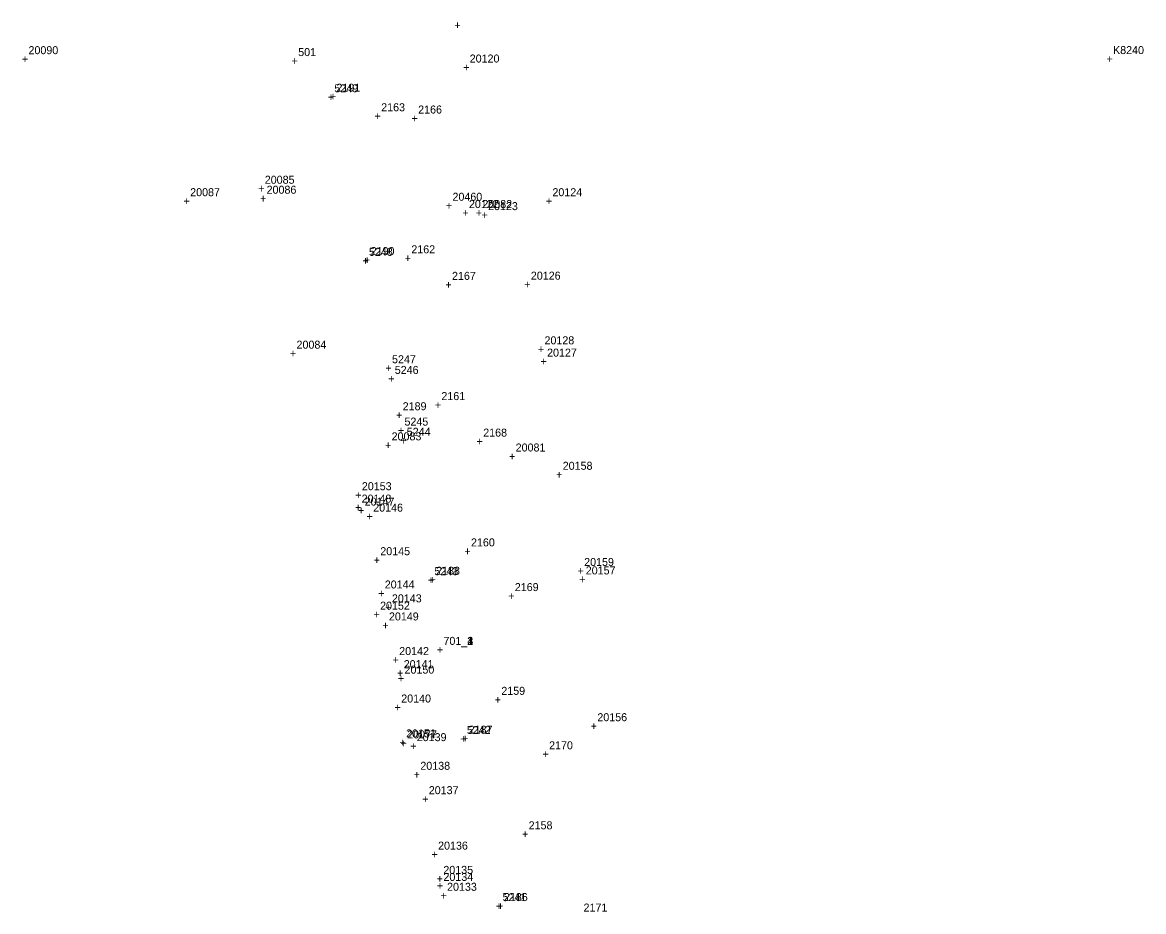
# Model space of a CAD drawing. Extents: x 1036751 to 1042192, y 772604 to 785439.
# Drawn here: x 1041410.1 to 1041760.3, y 774203.6 to 774481.3 of the extents above; entities that cross this region are included whole.
import ezdxf

# ---------------------------------------------------------------- set-up
doc = ezdxf.new("R2010")
doc.units = 0
for name, color, linetype in [('S_Buildings', 7, 'Continuous'), ('S_Buildings_SillElevation', 7, 'Continuous'), ('S_Control_Temp_Traverse', 7, 'Continuous'), ('S_Control_Traverse_Point', 7, 'Continuous'), ('S_Curb_Type_2', 7, 'Continuous'), ('S_Property_IronPipeFound', 7, 'Continuous'), ('S_Property_StoneWall', 7, 'Continuous'), ('S_Roadway_Centerline', 7, 'Continuous'), ('S_Roadway_Edge_Pavement', 7, 'Continuous'), ('S_Roadway_Monument', 7, 'Continuous'), ('S_Trees_Decid_Pay', 7, 'Continuous'), ('S_Utilities_Pole_Power', 7, 'Continuous'), ('S_Utilities_UG_Sanitary_MH', 7, 'Continuous')]:
    doc.layers.add(name, color=color, linetype=linetype)

msp = doc.modelspace()

# ---------------------------------------------------------------- texts
at = {"layer": 'S_Buildings'}
for s, p in [('20120', (1041549.8, 774468.8)), ('+', (1041547.74, 774466.05)), ('20085', (1041485.78, 774430.94)), ('20087', (1041462.48, 774427.05)), ('+', (1041483.72, 774428.19)), ('+', (1041460.42, 774424.3)), ('+', (1041566.84, 774398.22)), ('20126', (1041568.9, 774400.97)), ('20084', (1041495.7, 774379.42)), ('20127', (1041573.97, 774376.94)), ('+', (1041493.64, 774376.67)), ('+', (1041571.91, 774374.19)), ('+', (1041576.78, 774338.84)), ('20158', (1041578.85, 774341.59)), ('20157', (1041586.05, 774308.91)), ('+', (1041583.99, 774306.16))]:
    msp.add_text(s, height=2.5, dxfattribs=at).set_placement(p)
at = {"layer": 'S_Buildings_SillElevation'}
for s, p in [('+', (1041545, 774479.23)), ('20086', (1041486.35, 774427.82)), ('+', (1041484.29, 774425.07)), ('20128', (1041573.16, 774380.78)), ('+', (1041571.1, 774378.03)), ('20159', (1041585.55, 774311.54)), ('+', (1041583.49, 774308.79))]:
    msp.add_text(s, height=2.5, dxfattribs=at).set_placement(p)
at = {"layer": 'S_Control_Temp_Traverse'}
for s, p in [('701', (1041541.6, 774286.89)), ('701', (1041541.6, 774286.89)), ('701_4', (1041541.6, 774286.89)), ('701_3', (1041541.6, 774286.89)), ('701_2', (1041541.6, 774286.89)), ('701_1', (1041541.6, 774286.89)), ('+', (1041539.54, 774284.15)), ('+', (1041539.54, 774284.15)), ('+', (1041539.54, 774284.15)), ('+', (1041539.54, 774284.15)), ('+', (1041539.54, 774284.15)), ('+', (1041539.54, 774284.15))]:
    msp.add_text(s, height=2.5, dxfattribs=at).set_placement(p)
at = {"layer": 'S_Control_Traverse_Point'}
for s, p in [('501', (1041496.22, 774470.82)), ('501', (1041496.22, 774470.82)), ('501', (1041496.22, 774470.82)), ('501', (1041496.22, 774470.82)), ('501', (1041496.22, 774470.82)), ('501', (1041496.22, 774470.82)), ('501', (1041496.22, 774470.82)), ('501', (1041496.22, 774470.82)), ('501', (1041496.22, 774470.82)), ('501', (1041496.22, 774470.82)), ('+', (1041494.16, 774468.07)), ('+', (1041494.16, 774468.07)), ('+', (1041494.16, 774468.07)), ('+', (1041494.16, 774468.07)), ('+', (1041494.16, 774468.07)), ('+', (1041494.16, 774468.07)), ('+', (1041494.16, 774468.07)), ('+', (1041494.16, 774468.07)), ('+', (1041494.16, 774468.07)), ('+', (1041494.16, 774468.07))]:
    msp.add_text(s, height=2.5, dxfattribs=at).set_placement(p)
at = {"layer": 'S_Curb_Type_2'}
for s, p in [('5249', (1041507.52, 774459.51)), ('+', (1041505.46, 774456.76)), ('5248', (1041518.33, 774408.42)), ('+', (1041516.27, 774405.67)), ('5247', (1041525.53, 774374.87)), ('+', (1041523.47, 774372.12)), ('5246', (1041526.38, 774371.53)), ('+', (1041524.32, 774368.78)), ('+', (1041527.36, 774352.64)), ('5245', (1041529.42, 774355.39)), ('5244', (1041530.12, 774352.21)), ('+', (1041528.06, 774349.46)), ('5243', (1041538.78, 774308.67)), ('+', (1041536.72, 774305.92)), ('5242', (1041548.91, 774259.06)), ('+', (1041546.85, 774256.31)), ('5241', (1041560.05, 774206.84)), ('+', (1041557.98, 774204.09))]:
    msp.add_text(s, height=2.5, dxfattribs=at).set_placement(p)
at = {"layer": 'S_Property_IronPipeFound'}
for s, p in [('20082', (1041553.75, 774423.35)), ('+', (1041551.69, 774420.6))]:
    msp.add_text(s, height=2.5, dxfattribs=at).set_placement(p)
at = {"layer": 'S_Property_StoneWall'}
for s, p in [('20124', (1041575.64, 774427.04)), ('20122', (1041549.56, 774423.35)), ('20123', (1041555.54, 774422.7)), ('+', (1041573.58, 774424.29)), ('+', (1041547.49, 774420.6)), ('+', (1041553.48, 774419.95)), ('20153', (1041516.11, 774335.21)), ('+', (1041514.05, 774332.46)), ('20152', (1041521.8, 774297.89)), ('+', (1041519.74, 774295.14)), ('20151', (1041529.92, 774257.99)), ('20077', (1041530.27, 774257.67)), ('+', (1041527.86, 774255.24)), ('+', (1041528.21, 774254.92))]:
    msp.add_text(s, height=2.5, dxfattribs=at).set_placement(p)
at = {"layer": 'S_Roadway_Centerline'}
for s, p in [('+', (1041520.09, 774450.83)), ('2163', (1041522.15, 774453.58)), ('2162', (1041531.56, 774409.2)), ('+', (1041529.5, 774406.45)), ('2161', (1041540.95, 774363.36)), ('+', (1041538.89, 774360.61)), ('2160', (1041550.2, 774317.66)), ('+', (1041548.14, 774314.91)), ('+', (1041557.61, 774268.54)), ('2159', (1041559.67, 774271.29)), ('+', (1041566.15, 774226.54)), ('2158', (1041568.21, 774229.29))]:
    msp.add_text(s, height=2.5, dxfattribs=at).set_placement(p)
at = {"layer": 'S_Roadway_Edge_Pavement'}
for s, p in [('2191', (1041508.17, 774459.69)), ('+', (1041506.1, 774456.94)), ('2166', (1041533.7, 774452.87)), ('+', (1041531.64, 774450.12)), ('2190', (1041518.86, 774408.65)), ('+', (1041516.79, 774405.9)), ('+', (1041542.21, 774398.16)), ('2167', (1041544.27, 774400.91)), ('2189', (1041528.86, 774360.19)), ('+', (1041526.8, 774357.44)), ('+', (1041551.95, 774349.2)), ('2168', (1041554.02, 774351.95)), ('2188', (1041539.32, 774308.8)), ('+', (1041537.26, 774306.05)), ('2169', (1041563.89, 774303.7)), ('+', (1041561.83, 774300.95)), ('2187', (1041549.47, 774259.16)), ('+', (1041547.41, 774256.41)), ('2170', (1041574.6, 774254.28)), ('+', (1041572.54, 774251.53)), ('2186', (1041560.49, 774206.86)), ('+', (1041558.43, 774204.11)), ('2171', (1041585.36, 774203.59))]:
    msp.add_text(s, height=2.5, dxfattribs=at).set_placement(p)
at = {"layer": 'S_Roadway_Monument'}
for s, p in [('20081', (1041564.15, 774347.3)), ('+', (1041562.09, 774344.55))]:
    msp.add_text(s, height=2.5, dxfattribs=at).set_placement(p)
at = {"layer": 'S_Trees_Decid_Pay'}
for s, p in [('20148', (1041516.03, 774331.34)), ('+', (1041513.97, 774328.59)), ('20147', (1041516.99, 774330.39)), ('20146', (1041519.66, 774328.52)), ('+', (1041514.93, 774327.64)), ('+', (1041517.6, 774325.77)), ('20145', (1041521.87, 774314.91)), ('+', (1041519.81, 774312.16)), ('20144', (1041523.26, 774304.51)), ('+', (1041521.2, 774301.76)), ('20143', (1041525.49, 774300.18)), ('+', (1041523.43, 774297.43)), ('20149', (1041524.57, 774294.53)), ('+', (1041522.51, 774291.78)), ('20142', (1041527.77, 774283.72)), ('+', (1041525.71, 774280.97)), ('20141', (1041529.18, 774279.62)), ('+', (1041527.11, 774276.87)), ('20150', (1041529.44, 774277.91)), ('+', (1041527.38, 774275.16)), ('20140', (1041528.41, 774268.89)), ('+', (1041526.34, 774266.14)), ('20156', (1041589.67, 774263.05)), ('+', (1041587.61, 774260.3)), ('20139', (1041533.26, 774256.82)), ('+', (1041531.2, 774254.07)), ('20138', (1041534.38, 774247.87)), ('+', (1041532.32, 774245.12)), ('20137', (1041537.01, 774240.26)), ('+', (1041534.95, 774237.51)), ('20136', (1041539.92, 774222.94)), ('+', (1041537.86, 774220.19)), ('+', (1041539.5, 774212.61)), ('20135', (1041541.56, 774215.36)), ('20134', (1041541.59, 774213.16)), ('+', (1041539.53, 774210.41)), ('20133', (1041542.73, 774210.08)), ('+', (1041540.67, 774207.33))]:
    msp.add_text(s, height=2.5, dxfattribs=at).set_placement(p)
at = {"layer": 'S_Utilities_Pole_Power'}
for s, p in [('20090', (1041411.97, 774471.41)), ('+', (1041409.91, 774468.66)), ('20083', (1041525.4, 774350.78)), ('+', (1041523.34, 774348.03))]:
    msp.add_text(s, height=2.5, dxfattribs=at).set_placement(p)
at = {"layer": 'S_Utilities_UG_Sanitary_MH'}
for s, p in [('K8240', (1041750.77, 774471.44)), ('+', (1041748.71, 774468.69)), ('+', (1041542.35, 774422.87)), ('20460', (1041544.42, 774425.62))]:
    msp.add_text(s, height=2.5, dxfattribs=at).set_placement(p)

doc.saveas('drawing.dxf')
